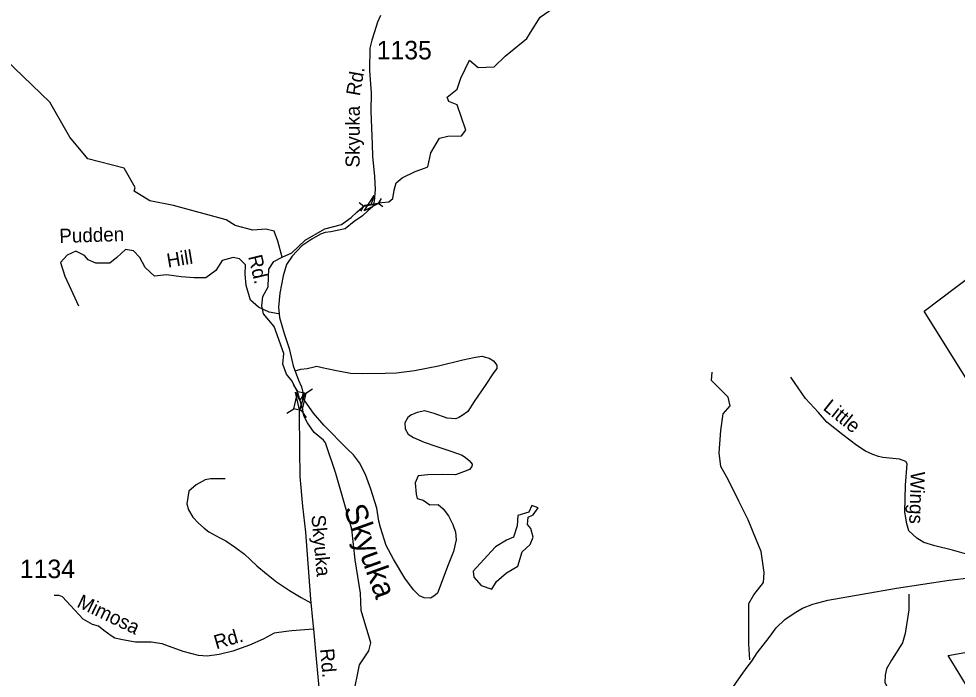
# Model space of a CAD drawing. Extents: x 990631 to 1056237, y 535999 to 585651.
# Drawn here: x 1032860 to 1039191, y 557410 to 561861 of the extents above; entities that cross this region are included whole.
import ezdxf

# ---------------------------------------------------------------- set-up
doc = ezdxf.new("R2010")
doc.units = 0
for name, color, linetype in [('Exist Boundary Political City Limit New', 7, 'Continuous'), ('Exist Hydrographic Creek Single Shore', 7, 'Continuous'), ('Exist Hydrographic Creek Single Shore Label', 7, 'Continuous'), ('Exist Hydrographic Pond Over 1500 Sq Ft', 7, 'Continuous'), ('Exist Road Non-System Type 51', 7, 'Continuous'), ('Exist Road Non-System Type 51 Label', 7, 'Continuous'), ('Exist Road Primary NC Attributed', 7, 'Continuous'), ('Exist Road Primary US Structure Standard Bridge CELL', 7, 'Continuous'), ('Exist Road Secondary Structure Pipe Attributed CELL', 7, 'Continuous'), ('Exist Road Secondary Structure Pipe CELL', 7, 'Continuous'), ('Exist Road Secondary Structure Standard Bridge Attributed CELL', 7, 'Continuous'), ('Exist Road Secondary Type 51 Attributed', 7, 'Continuous'), ('Exist Road Secondary Type 51 Label', 7, 'Continuous'), ('Exist Road Secondary Type 51 Number Label', 7, 'Continuous')]:
    doc.layers.add(name, color=color, linetype=linetype)

msp = doc.modelspace()

# ---------------------------------------------------------------- linework, layer by layer
at = {"layer": 'Exist Boundary Political City Limit New'}
for points in [[(1039357.1, 559263.7), (1038967.6, 559887.1), (1039740.5, 560469.5)], [(1039254.6, 557360.5), (1039130.8, 557564), (1040003.6, 557720.6)]]:
    msp.add_lwpolyline(points, dxfattribs=at)
at = {"layer": 'Exist Hydrographic Creek Single Shore'}
for points in [[(1036140.8, 561607.7), (1036287.6, 561727.9), (1036312.4, 561767.6), (1036378.6, 561872.9), (1036530.7, 561978.2), (1036596.9, 562177.1), (1036686.6, 562329.2), (1036725.6, 562547.6), (1036741.2, 562723.2), (1036830.8, 562871.4), (1036982.9, 562926), (1037154.4, 562968.9), (1037200.1, 563138.5), (1037089.8, 563361.2), (1037044.6, 563559.5)], [(1034636.9, 560251.6), (1034608.1, 560359.3), (1034582.1, 560427.4), (1034526.1, 560441.4), (1034440, 560435.4), (1034319.8, 560465.8), (1034258.5, 560503.5), (1033904.3, 560600.3), (1033744.2, 560632.4), (1033638.3, 560697.4), (1033644.4, 560722.3), (1033571.4, 560852.1), (1033325.5, 560915.7), (1033205.1, 561062.5), (1033070.7, 561298.3), (1032706.7, 561643.7), (1032635.7, 561750.1)], [(1034636.9, 560251.6), (1034701.8, 560281.9), (1034791.9, 560366.6), (1034926, 560442.7), (1035038.1, 560472.8), (1035102.1, 560520.8), (1035140.1, 560554.9), (1035194.2, 560602.9), (1035310.3, 560621), (1035356.3, 560625), (1035384.3, 560647), (1035392.3, 560705.1), (1035406.3, 560753.2), (1035446.4, 560787.2), (1035534.4, 560829.3), (1035596.5, 560853.3), (1035620.5, 560861.3), (1035640.5, 560956.8), (1035698.1, 561055.1), (1035754, 561067.7), (1035846, 561071.8), (1035875.3, 561109.5), (1035816.7, 561280.9), (1035762.4, 561301.9), (1035749.9, 561331.1), (1035816.7, 561385.5), (1035841.8, 561460.8), (1035900.4, 561582), (1035958.9, 561531.9), (1036067.6, 561536), (1036140.8, 561607.7)], [(1035117, 557289.7), (1035159, 557500), (1035221, 557594.1), (1035235, 557650.2), (1035169, 557866.5), (1035164.5, 557983.9), (1035128.9, 558209.6), (1035106.9, 558415.9), (1034999.4, 558792.9), (1034929.3, 558999.2), (1034915.8, 559017.5), (1034853.8, 559068.6), (1034808.8, 559134.5), (1034783.8, 559180.5), (1034776.8, 559221.6), (1034743.2, 559336.7), (1034705.2, 559414.9), (1034667.2, 559462.9), (1034641.2, 559531), (1034649.2, 559603.1), (1034584.1, 559784.5), (1034510.1, 559868.6), (1034500.1, 559922.7), (1034506.1, 559986.8), (1034542.1, 560052.9), (1034544.1, 560117), (1034546.1, 560171), (1034581.8, 560221.8), (1034636.9, 560251.6)]]:
    msp.add_lwpolyline(points, dxfattribs=at)
at = {"layer": 'Exist Hydrographic Pond Over 1500 Sq Ft'}
msp.add_lwpolyline([(1035925.2, 558133.3), (1035929.4, 558091.5), (1035979.5, 558037.1), (1036050.6, 558012), (1036084, 558062.2), (1036150.9, 558120.8), (1036226.2, 558166.8), (1036255.4, 558263), (1036309.8, 558313.1), (1036330.7, 558363.3), (1036314, 558421.9), (1036293.1, 558447), (1036297.2, 558497.1), (1036330.7, 558513.9), (1036330.7, 558513.9), (1036364.1, 558559.9), (1036322.3, 558576.6), (1036301.4, 558530.6), (1036226.2, 558509.7), (1036222, 558438.6), (1036196.9, 558363.3), (1036150.9, 558342.4), (1036075.7, 558296.4), (1036021.3, 558237.9)], close=True, dxfattribs=at)
at = {"layer": 'Exist Road Non-System Type 51'}
for points in [[(1034612.3, 559869.3), (1034549.6, 559881.9), (1034478.5, 559915.3), (1034424.2, 559961.3), (1034394.9, 560061.7), (1034386.6, 560137), (1034390.8, 560199.7), (1034349, 560241.5), (1034307.2, 560249.9), (1034231.9, 560229), (1034190.1, 560162.1), (1034123.2, 560111.9), (1034043.8, 560111.9), (1033956, 560120.3), (1033855.7, 560132.8), (1033776.3, 560124.4), (1033713.6, 560183), (1033676, 560249.9), (1033634.1, 560295.9), (1033579.8, 560304.3), (1033521.3, 560249.9), (1033475.3, 560212.3), (1033379.2, 560212.3), (1033329, 560233.2), (1033303.9, 560262.4), (1033245.4, 560291.7), (1033186.9, 560266.6), (1033140.9, 560216.4), (1033170.1, 560124.4), (1033224.5, 560007.3), (1033262.1, 559923.7)], [(1034725.5, 559485.3), (1034761.9, 559495.6), (1034806.2, 559500.4), (1034853.3, 559513), (1034870, 559515.7), (1034907.8, 559506.6), (1034991.4, 559489), (1035097.1, 559469.4), (1035179.1, 559466.8), (1035331.4, 559469.9), (1035407.4, 559471.4), (1035530, 559487.5), (1035691.1, 559518.3), (1035856.6, 559559.2), (1035941.1, 559576.5), (1035985.3, 559585), (1035999.2, 559580.5), (1036033.1, 559571.4), (1036062.5, 559552.4), (1036085.5, 559523.8), (1036084.9, 559501.8), (1036063.8, 559470.4), (1036007.1, 559386.1), (1035933.5, 559278.5), (1035889.3, 559209.8), (1035852.4, 559182.9), (1035828.1, 559169.8), (1035807.7, 559160.4), (1035749.8, 559166.2), (1035662.8, 559197.1), (1035599.3, 559215), (1035546.9, 559204.7), (1035504.3, 559186.1), (1035485.8, 559170.7), (1035463.7, 559133.9), (1035466.3, 559093.8), (1035486.3, 559057.5), (1035523.5, 559035.5), (1035594.5, 559003), (1035673.8, 558976.6), (1035780.7, 558941.1), (1035851.8, 558914.8), (1035873.3, 558900.2), (1035898.7, 558879.3), (1035918, 558854.7), (1035917.5, 558838.7), (1035900.9, 558819.2), (1035860.3, 558802.4), (1035807.5, 558782.1), (1035719.5, 558785.1), (1035619.4, 558782.3), (1035555.1, 558775.6), (1035533.5, 558728.2), (1035541.2, 558652.6), (1035548.4, 558624.4), (1035588, 558611), (1035632.6, 558580.8), (1035689, 558581.8), (1035724.3, 558554.7), (1035758.7, 558505.6), (1035788.8, 558448.5), (1035807.1, 558395.9), (1035811.5, 558343.6), (1035793.1, 558266.2), (1035756.1, 558175.3), (1035686, 557985.4), (1035661.2, 557964.3), (1035636.9, 557951), (1035594.9, 557952.5), (1035563.2, 557965.5), (1035522.6, 558006.7), (1035465, 558086.7), (1035389.1, 558213.1), (1035338, 558307), (1035299.8, 558428.2), (1035289.2, 558470.6), (1035276, 558559.1), (1035236.2, 558686.3), (1035199.4, 558785.7), (1035157.7, 558865), (1035117.4, 558918.4), (1035078.5, 558955.6), (1034917.8, 559118.9), (1034848.4, 559199.1), (1034773.8, 559303.9)], [(1037793.1, 557534.7), (1037784.7, 557643.4), (1037784.7, 557739.6), (1037784.7, 557844.1), (1037784.7, 557915.2), (1037818.1, 557973.8), (1037885, 558057.4), (1037889.2, 558124.3), (1037868.3, 558266.5), (1037834.9, 558346), (1037780.5, 558479.8), (1037717.8, 558605.3), (1037646.8, 558751.6), (1037596.6, 558839.5), (1037584.1, 558931.5), (1037596.6, 559082), (1037613.3, 559194.9), (1037659.3, 559249.3), (1037646.8, 559307.8), (1037533.9, 559420.7), (1037538.1, 559475.1)], [(1039642.1, 558100.2), (1039432.6, 558180.8), (1039270.4, 558242.1), (1039159.4, 558273.8), (1039040.2, 558303.6), (1038965, 558325.9), (1038917.8, 558355.5), (1038865.3, 558405.2), (1038850.9, 558451.7), (1038837.5, 558530.2), (1038843.4, 558714.1), (1038853.9, 558857.9), (1038844.4, 558874.1), (1038800.9, 558889.6), (1038689, 558899.3), (1038659.4, 558906.3), (1038621.9, 558921.4), (1038572.5, 558943), (1038513.6, 558980.8), (1038419.8, 559052), (1038312.5, 559137.6), (1038254.6, 559203.3), (1038167.5, 559298.1), (1038068.2, 559441.6)], [(1034252, 558756), (1034154, 558757.2), (1034117.6, 558748.3), (1034056.6, 558716.3), (1034007.3, 558671.9), (1033999.8, 558630), (1033994.6, 558588.1), (1034005.1, 558545.9), (1034035.5, 558496.9), (1034072.4, 558457.5), (1034111.3, 558422.3), (1034142.4, 558397.3), (1034217.2, 558357), (1034256.6, 558337.6), (1034323.1, 558293.4), (1034383.8, 558247.4), (1034467.3, 558168.7), (1034531.6, 558114.8), (1034597.9, 558060.4), (1034686.2, 558001.6), (1034764.7, 557955), (1034830.3, 557919.5)], [(1038865.7, 557977), (1038864.4, 557873), (1038839.2, 557711.6), (1038821.1, 557648.2), (1038747.3, 557532.4), (1038713.5, 557473.5), (1038706.1, 557431.8), (1038702.5, 557381.9), (1038723.3, 557343), (1038808.2, 557248.3), (1038899.5, 557163.4), (1038974.3, 557062.9), (1038991.6, 557036.3), (1039021.5, 556971.3), (1039045.2, 556834.4)]]:
    msp.add_lwpolyline(points, dxfattribs=at)
at = {"layer": 'Exist Road Primary NC Attributed'}
msp.add_lwpolyline([(1037606, 557245.1), (1037732.7, 557428.1), (1037773.6, 557485.8), (1037806, 557525.5), (1037842.4, 557581.4), (1037922.6, 557684.3), (1037969.5, 557750.5), (1038027.2, 557805.8), (1038091, 557850.4), (1038146.3, 557882.8), (1038217.2, 557910.5), (1038319.4, 557937), (1038782.3, 558018.8), (1039136.9, 558071.7), (1039448.3, 558109)], dxfattribs=at)
at = {"layer": 'Exist Road Primary US Structure Standard Bridge CELL'}
for p, q in [((1034742.2, 559346.3), (1034712.5, 559392.9)), ((1034796, 559334.4), (1034842.6, 559364)), ((1034669.1, 559198.7), (1034715.7, 559228.4)), ((1034800.5, 559169.6), (1034770.8, 559216.1))]:
    msp.add_line(p, q, dxfattribs=at)
msp.add_lwpolyline([(1034715.7, 559228.4), (1034741.9, 559346.4), (1034797, 559334.2), (1034770.8, 559216.1)], close=True, dxfattribs=at)
at = {"layer": 'Exist Road Secondary Structure Pipe Attributed CELL'}
msp.add_lwpolyline([(1035299.5, 560621.2), (1035191.1, 560565.3), (1035257, 560667.9), (1035236.2, 560606.3)], close=True, dxfattribs=at)
at = {"layer": 'Exist Road Secondary Structure Pipe CELL'}
for p, q in [((1035305.8, 560648.8), (1035283.8, 560614.6)), ((1035155.8, 560620.4), (1035188.8, 560596.6)), ((1035166.8, 560562.4), (1035188.8, 560596.6)), ((1035188.8, 560596.6), (1035283.8, 560614.6)), ((1035316.7, 560590.8), (1035283.8, 560614.6))]:
    msp.add_line(p, q, dxfattribs=at)
at = {"layer": 'Exist Road Secondary Structure Standard Bridge Attributed CELL'}
msp.add_lwpolyline([(1034790.6, 559336.9), (1034753.2, 559220.9), (1034727.5, 559340.1), (1034756.2, 559281.8)], close=True, dxfattribs=at)
at = {"layer": 'Exist Road Secondary Type 51 Attributed'}
for points in [[(1035301.3, 561883.4), (1035281.2, 561839.2), (1035261, 561772), (1035241.3, 561716.5), (1035227.8, 561662.7), (1035226.7, 561513.9), (1035230.6, 561449.8), (1035237.1, 561360.2), (1035234.4, 561237.1), (1035245.1, 561012.3), (1035246.4, 560933.4), (1035259.8, 560795.6), (1035263.8, 560709.9), (1035257.1, 560631), (1035247.8, 560593.5), (1035215.7, 560564.1), (1035179.6, 560530.6), (1035123.4, 560493.2), (1035062.3, 560444.5), (1034965.6, 560423.6), (1034926.9, 560418.3), (1034896.1, 560407.5), (1034837.3, 560372.8), (1034770.4, 560328.6), (1034704.9, 560259), (1034666.1, 560202.8), (1034643.4, 560126.6), (1034622, 560008.8), (1034611.3, 559915.2), (1034618, 559844.2), (1034651.4, 559735.9), (1034683.5, 559635.5), (1034711.6, 559519.1), (1034746.3, 559422.8), (1034767.7, 559375.9), (1034777.1, 559338.5), (1034774.4, 559310.4), (1034773.5, 559286.2), (1034762, 559243.1)], [(1034762, 559243.1), (1034752.5, 559207.4), (1034754.3, 558951.7), (1034756, 558771.3), (1034775.3, 558571.7), (1034794.5, 558396.5), (1034827.9, 557944.3), (1034843.5, 557781.9), (1034847.4, 557741)], [(1034847.4, 557741), (1034701.8, 557731.1), (1034665, 557725.8), (1034582.8, 557715.3), (1034509.2, 557673.3), (1034416.5, 557633), (1034304.5, 557592.7), (1034211.7, 557570), (1034131.2, 557559.5), (1034071.7, 557563), (1033970.2, 557591), (1033828.4, 557643.5), (1033753.2, 557654), (1033648.2, 557654), (1033560.7, 557669.8), (1033508.2, 557680.3), (1033483.7, 557696), (1033432.9, 557732.8), (1033397.9, 557762.6), (1033357.6, 557773.1), (1033294.6, 557808.1), (1033236.9, 557872.9), (1033154.6, 557958.7), (1033131.9, 557969.2), (1033102.1, 557969.2), (1033099.1, 557968.9)], [(1034847.4, 557741), (1034868, 557517.4), (1034889, 557300.3), (1034929.3, 557130.4), (1034947, 557051.4)]]:
    msp.add_lwpolyline(points, dxfattribs=at)

# ---------------------------------------------------------------- texts
at = {"layer": 'Exist Hydrographic Creek Single Shore Label'}
msp.add_text('Skyuka', height=150, rotation=289.70713, dxfattribs=at).set_placement((1035049.7, 558555))
at = {"layer": 'Exist Road Non-System Type 51 Label'}
for s, rotation, p in [('Pudden', 1.70877, (1033134.9, 560348)), ('Hill', 9.25703, (1033866.3, 560181.1)), ('Rd.', 283.51829, (1034406.9, 560256.1)), ('Little', 321.42414, (1038280.1, 559226.3)), ('Wings', 268.16043, (1038878.4, 558806.1))]:
    msp.add_text(s, height=95, rotation=rotation, dxfattribs=at).set_placement(p)
at = {"layer": 'Exist Road Secondary Type 51 Label'}
for s, rotation, p in [('Rd.', 80.02729, (1035160.6, 561335.9)), ('Skyuka', 89.82752, (1035159.7, 560856.6)), ('Skyuka', 275.1122, (1034833.7, 558508.9)), ('Mimosa', 334.4139, (1033245.8, 557894.6)), ('Rd.', 16.16569, (1034192.4, 557604.9)), ('Rd.', 275.19749, (1034892, 557607.2))]:
    msp.add_text(s, height=95, rotation=rotation, dxfattribs=at).set_placement(p)
at = {"layer": 'Exist Road Secondary Type 51 Number Label'}
for s, p in [('1135', (1035274.9, 561587)), ('1134', (1032867.5, 558085.8))]:
    msp.add_text(s, height=125, dxfattribs=at).set_placement(p)

doc.saveas('drawing.dxf')
